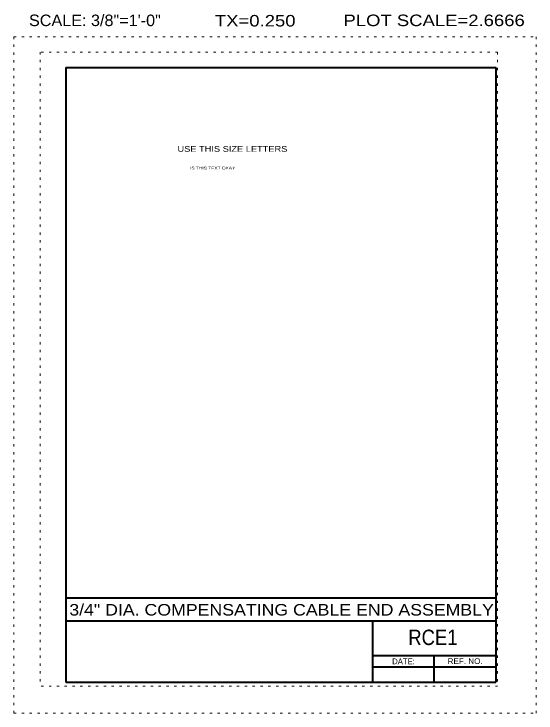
# Model space of a CAD drawing. Extents: x 1370 to 1392.7, y -905.5 to -875.2.
import ezdxf
from ezdxf.enums import TextEntityAlignment as Align

# ---------------------------------------------------------------- set-up
doc = ezdxf.new("R2010")
doc.units = 0
doc.header["$LTSCALE"] = 0.2
doc.linetypes.add('DOTTED', pattern=[1.5, 0.3, -1.2])
for name, color, linetype in [('57', 7, 'Continuous'), ('58', 7, 'Continuous'), ('59', 7, 'Continuous'), ('8', 7, 'Continuous'), ('9', 7, 'Continuous')]:
    doc.layers.add(name, color=color, linetype=linetype)
for name, color, linetype, lineweight in [('61', 7, 'DOTTED', 13), ('62', 7, 'DOTTED', 13), ('63', 7, 'Continuous', 40)]:
    doc.layers.add(name, color=color, linetype=linetype, lineweight=lineweight)

msp = doc.modelspace()

# ---------------------------------------------------------------- linework, layer by layer
at = {"layer": '61'}
for p, q in [((1391.0168, -876.8388), (1371.1491, -876.8388)), ((1371.1491, -876.8388), (1371.1491, -904.3521)), ((1391.0168, -876.8388), (1391.0168, -904.3521)), ((1391.0168, -904.3521), (1371.1491, -904.3521))]:
    msp.add_line(p, q, dxfattribs=at)
at = {"layer": '62'}
for p, q in [((1370.0158, -905.5121), (1370.0158, -876.1787)), ((1370.0158, -876.1787), (1392.6834, -876.1787)), ((1392.6834, -905.5121), (1392.6834, -876.1787)), ((1370.0158, -905.5121), (1392.6834, -905.5121))]:
    msp.add_line(p, q, dxfattribs=at)
at = {"layer": '63'}
for p, q in [((1372.2658, -877.5121), (1372.2658, -904.1787)), ((1372.2658, -877.5121), (1390.9334, -877.5121)), ((1390.9334, -877.5121), (1390.9334, -904.1787)), ((1372.2658, -900.5121), (1390.9334, -900.5121)), ((1372.2658, -901.5121), (1390.9334, -901.5121)), ((1385.5997, -904.1787), (1385.5997, -901.5121)), ((1385.5997, -903.0121), (1390.9334, -903.0121)), ((1388.2668, -904.1787), (1388.2668, -903.0121)), ((1385.5997, -903.5121), (1390.9334, -903.5121)), ((1372.2658, -904.1787), (1390.9334, -904.1787))]:
    msp.add_line(p, q, dxfattribs=at)

# ---------------------------------------------------------------- texts
at = {"layer": '57', "width": 1.15}
msp.add_text('3/4" DIA. COMPENSATING CABLE END ASSEMBLY', height=0.5, dxfattribs=at).set_placement((1381.6354, -901.2831), align=Align.CENTER)
at = {"layer": '58', "width": 0.9}
msp.add_text('RCE1', height=0.6667, dxfattribs=at).set_placement((1388.2062, -902.5627), align=Align.CENTER)
at = {"layer": '59'}
msp.add_text('DATE:', height=0.2502, dxfattribs=at).set_placement((1386.9297, -903.3947), align=Align.CENTER)
at = {"layer": '59', "width": 1.05}
msp.add_text('REF. NO.', height=0.2503, dxfattribs=at).set_placement((1389.6055, -903.3861), align=Align.CENTER)
at = {"layer": '8'}
for s, height, width, p in [('USE THIS SIZE LETTERS', 0.25, 1.2, (1377.1163, -881.1641)), ('IS THIS TEXT OKAY', 0.125, 1.25, (1377.6626, -881.9308))]:
    msp.add_text(s, height=height, dxfattribs=dict(at, width=width)).set_placement(p)
at = {"layer": '9'}
for s, width, p in [('SCALE: 3/8"=1\'-0"', 1.05, (1373.5306, -875.7104)), ('TX=0.250', 1.2, (1380.4908, -875.7267)), ('PLOT SCALE=2.6666', 1.2, (1388.2583, -875.7104))]:
    msp.add_text(s, height=0.5, dxfattribs=dict(at, width=width)).set_placement(p, align=Align.CENTER)

doc.saveas('drawing.dxf')
